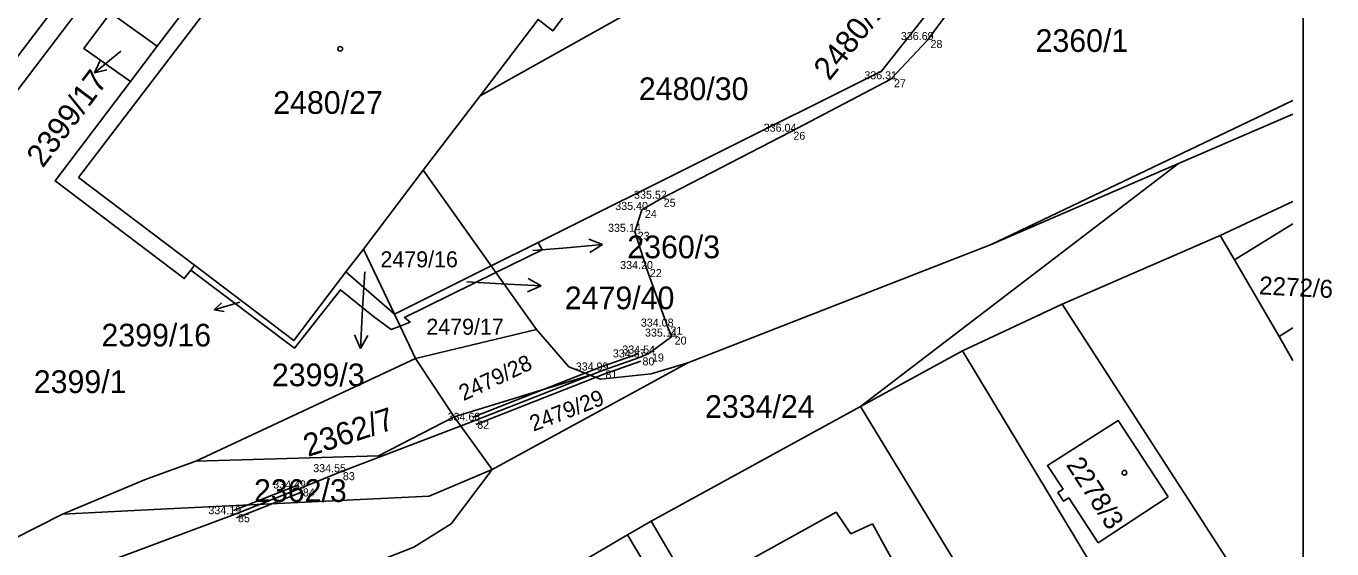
# Model space of a CAD drawing. Extents: x -606208 to -605570, y -1157873 to -1157573.
# Drawn here: x -605669 to -605571.1, y -1157686.5 to -1157647.4 of the extents above; entities that cross this region are included whole.
import ezdxf

# ---------------------------------------------------------------- set-up
doc = ezdxf.new("R2010")
doc.units = 0
for name, color, linetype in [('Vrstva 1', 7, 'Continuous'), ('Vrstva 30', 7, 'Continuous'), ('Vrstva 38', 7, 'Continuous'), ('Vrstva 58', 7, 'Continuous'), ('Vrstva 59', 7, 'Continuous'), ('Vrstva 60', 7, 'Continuous'), ('Vrstva 62', 7, 'Continuous')]:
    doc.layers.add(name, color=color, linetype=linetype)

msp = doc.modelspace()

# ---------------------------------------------------------------- linework, layer by layer
at = {"layer": 'Vrstva 1'}
msp.add_lwpolyline([(-606203.28, -1157873.46), (-605573.29, -1157873.46), (-605573.29, -1157576.47), (-606203.28, -1157576.47)], close=True, dxfattribs=at)
at = {"layer": 'Vrstva 30'}
msp.add_lwpolyline([(-605665.67, -1157688.53), (-605653.37, -1157683.93), (-605648.51, -1157682), (-605645.51, -1157680.78), (-605635.44, -1157676.93), (-605625.83, -1157673.16), (-605623.05, -1157672.18), (-605622.34, -1157671.89), (-605620.64, -1157670.62), (-605620.95, -1157669.87), (-605622.5, -1157665.56), (-605623.41, -1157662.77), (-605622.87, -1157661.13), (-605621.46, -1157660.29), (-605611.74, -1157655.27), (-605604.2, -1157651.34), (-605601.46, -1157648.4), (-605597.74, -1157643.37)], dxfattribs=at)
at = {"layer": 'Vrstva 38'}
for p, q in [((-605648.62, -1157681.72), (-605653.48, -1157683.65)), ((-605648.4, -1157682.28), (-605653.26, -1157684.21))]:
    msp.add_line(p, q, dxfattribs=at)
for points in [[(-605623.15, -1157671.9), (-605625.93, -1157672.88), (-605635.55, -1157676.65)], [(-605622.95, -1157672.46), (-605625.73, -1157673.44), (-605635.33, -1157677.21)]]:
    msp.add_lwpolyline(points, dxfattribs=at)
at = {"layer": 'Vrstva 60'}
for p, q in [((-605601.46, -1157648.4), (-605601.46, -1157648.4)), ((-605604.2, -1157651.34), (-605604.2, -1157651.34)), ((-605611.74, -1157655.27), (-605611.74, -1157655.27)), ((-605621.46, -1157660.29), (-605621.46, -1157660.29)), ((-605622.87, -1157661.13), (-605622.87, -1157661.13)), ((-605623.41, -1157662.77), (-605623.41, -1157662.77)), ((-605622.5, -1157665.56), (-605622.5, -1157665.56)), ((-605620.95, -1157669.87), (-605620.95, -1157669.87)), ((-605620.64, -1157670.62), (-605620.64, -1157670.62)), ((-605623.05, -1157672.18), (-605623.05, -1157672.18)), ((-605622.34, -1157671.89), (-605622.34, -1157671.89)), ((-605625.83, -1157673.16), (-605625.83, -1157673.16)), ((-605635.44, -1157676.93), (-605635.44, -1157676.93)), ((-605645.51, -1157680.78), (-605645.51, -1157680.78)), ((-605648.51, -1157682), (-605648.51, -1157682)), ((-605653.37, -1157683.93), (-605653.37, -1157683.93))]:
    msp.add_line(p, q, dxfattribs=at)
at = {"layer": 'Vrstva 62'}
for p, q in [((-605653.95, -1157631.43), (-605678, -1157663.1)), ((-605659.2, -1157648.85), (-605651.64, -1157638.87)), ((-605665.1, -1157658.71), (-605651.37, -1157640.68)), ((-605635, -1157652.57), (-605615.84, -1157641.85)), ((-605661.93, -1157649.24), (-605663.912, -1157650.845)), ((-605659.2, -1157648.85), (-605661.22, -1157651.51)), ((-605663.912, -1157650.845), (-605663.519, -1157649.979)), ((-605663.912, -1157650.845), (-605662.983, -1157650.64)), ((-605635, -1157652.57), (-605639.26, -1157658.16)), ((-605574.07, -1157652.93), (-605596.68, -1157663.73)), ((-605582.64, -1157657.66), (-605574.07, -1157653.96)), ((-605582.64, -1157657.66), (-605606.49, -1157675.87)), ((-605656.42, -1157665.28), (-605665.1, -1157658.71)), ((-605639.26, -1157658.16), (-605643.75, -1157664.06)), ((-605634.17, -1157665.31), (-605639.26, -1157658.16)), ((-605574.07, -1157660.5), (-605579.52, -1157663.05)), ((-605591.36, -1157668.19), (-605579.52, -1157663.05)), ((-605578.46, -1157664.86), (-605579.52, -1157663.05)), ((-605634.17, -1157665.31), (-605630.66, -1157663.56)), ((-605631.06, -1157664.17), (-605628.81, -1157663.99)), ((-605628.81, -1157663.99), (-605625.82, -1157663.728)), ((-605625.82, -1157663.728), (-605626.862, -1157663.317)), ((-605625.82, -1157663.728), (-605626.774, -1157664.315)), ((-605643.75, -1157664.06), (-605645.06, -1157665.78)), ((-605641.42, -1157668.93), (-605643.75, -1157664.06)), ((-605575.11, -1157670.61), (-605578.46, -1157664.86)), ((-605645.06, -1157665.78), (-605641.42, -1157668.93)), ((-605643.65, -1157665.76), (-605643.82, -1157668.52)), ((-605641.42, -1157668.93), (-605634.17, -1157665.31)), ((-605634.17, -1157665.31), (-605633.81, -1157665.82)), ((-605630.78, -1157670.08), (-605633.81, -1157665.82)), ((-605635.99, -1157666.52), (-605633.42, -1157666.66)), ((-605633.42, -1157666.66), (-605630.423, -1157666.817)), ((-605630.423, -1157666.817), (-605631.449, -1157667.265)), ((-605630.423, -1157666.817), (-605631.397, -1157666.265)), ((-605653, -1157668.05), (-605654.933, -1157668.604)), ((-605654.933, -1157668.604), (-605654.38, -1157668.097)), ((-605654.933, -1157668.604), (-605654.195, -1157668.742)), ((-605643.82, -1157668.52), (-605643.977, -1157671.517)), ((-605591.36, -1157668.19), (-605598.85, -1157671.69)), ((-605640.99, -1157669.83), (-605641.42, -1157668.93)), ((-605639.84, -1157672.25), (-605640.99, -1157669.83)), ((-605643.977, -1157671.517), (-605644.425, -1157670.491)), ((-605643.977, -1157671.517), (-605643.425, -1157670.543)), ((-605639.84, -1157672.25), (-605630.78, -1157670.08)), ((-605574.07, -1157672.4), (-605575.11, -1157670.61)), ((-605606.49, -1157675.87), (-605598.85, -1157671.69)), ((-605639.84, -1157672.25), (-605656.31, -1157679.96)), ((-605636.95, -1157676.63), (-605639.84, -1157672.25)), ((-605619.44, -1157672.59), (-605634.09, -1157680.59)), ((-605636.95, -1157676.63), (-605626.75, -1157673.51)), ((-605636.95, -1157676.63), (-605642.61, -1157679.56)), ((-605634.09, -1157680.59), (-605636.95, -1157676.63)), ((-605622.17, -1157684.45), (-605606.49, -1157675.87)), ((-605606.49, -1157675.87), (-605590.01, -1157702.84)), ((-605642.61, -1157679.56), (-605656.31, -1157679.96)), ((-605656.31, -1157679.96), (-605660.04, -1157681.31)), ((-605660.04, -1157681.31), (-605666.31, -1157683.93)), ((-605623.94, -1157685.48), (-605622.17, -1157684.45)), ((-605622.17, -1157684.45), (-605606.61, -1157711.04)), ((-605615.75, -1157687.9), (-605608.3, -1157683.78)), ((-605608.3, -1157683.78), (-605607.2, -1157685.39)), ((-605636.65, -1157692.89), (-605623.94, -1157685.48)), ((-605623.94, -1157685.48), (-605615.89, -1157699.06)), ((-605607.2, -1157685.39), (-605605.59, -1157684.64)), ((-605605.59, -1157684.64), (-605601.39, -1157692.27))]:
    msp.add_line(p, q, dxfattribs=at)
for points in [[(-605714.75, -1157700.25), (-605710.96, -1157695.68), (-605710.18, -1157694.65), (-605706.94, -1157690.4), (-605702.43, -1157684.48), (-605699.9, -1157681.15), (-605696.13, -1157676.2), (-605691.65, -1157670.31), (-605690.12, -1157670.1), (-605687.04, -1157672.45), (-605682.78, -1157666.84), (-605681.4, -1157665.03), (-605679.37, -1157662.36), (-605660.55, -1157637.61), (-605653.28, -1157627.99)], [(-605621.69, -1157637.35), (-605629.56, -1157647.72), (-605630.66, -1157646.86), (-605635, -1157652.57)], [(-605599.92, -1157644.4), (-605604.92, -1157650.72), (-605630.66, -1157663.56)], [(-605661.22, -1157651.51), (-605664.71, -1157649.03), (-605662.71, -1157646.36), (-605659.2, -1157648.85)], [(-605656.69, -1157665.64), (-605657.18, -1157666.27), (-605666.86, -1157658.96), (-605661.22, -1157651.51)], [(-605619.44, -1157672.59), (-605596.68, -1157663.73), (-605582.64, -1157657.66)], [(-605578.46, -1157664.86), (-605574.07, -1157662.17)], [(-605630.66, -1157663.56), (-605630.36, -1157664.12), (-605633.81, -1157665.82)], [(-605656.69, -1157665.64), (-605656.42, -1157665.28), (-605648.97, -1157670.92), (-605645.06, -1157665.78)], [(-605640.99, -1157669.83), (-605641.66, -1157670.1), (-605642.98, -1157669.11), (-605645.47, -1157667.11), (-605648.92, -1157671.49), (-605656.69, -1157665.64)], [(-605633.81, -1157665.82), (-605640.68, -1157669.2), (-605640.25, -1157669.53), (-605640.99, -1157669.83)], [(-605591.36, -1157668.19), (-605574.07, -1157694.95)], [(-605626.75, -1157673.51), (-605628.34, -1157672.88), (-605630.78, -1157670.08)], [(-605574.07, -1157669.97), (-605575.11, -1157670.61)], [(-605574.07, -1157711.46), (-605582.64, -1157698.54), (-605598.85, -1157671.69)], [(-605619.44, -1157672.59), (-605622.17, -1157673.4), (-605625.98, -1157673.81), (-605626.75, -1157673.51)], [(-605583.41, -1157682.62), (-605588.67, -1157686.07), (-605590.88, -1157682.71), (-605591.26, -1157682.96), (-605591.69, -1157682.31), (-605591.3, -1157682.05), (-605592.47, -1157680.28), (-605587.17, -1157676.9), (-605583.41, -1157682.62)], [(-605634.09, -1157680.59), (-605637.18, -1157684.66), (-605639.98, -1157686.4), (-605673.75, -1157699.63)], [(-605634.09, -1157680.59), (-605638.82, -1157682.58), (-605658.45, -1157683.53), (-605666.31, -1157683.93)], [(-605666.31, -1157683.93), (-605670.06, -1157685.83), (-605679.01, -1157689.56)]]:
    msp.add_lwpolyline(points, dxfattribs=at)
for centre in [(-605645.487, -1157649.059), (-605586.697, -1157680.819)]:
    msp.add_circle(centre, 0.175, dxfattribs=at)

# ---------------------------------------------------------------- texts
at = {"layer": 'Vrstva 58'}
for s, p in [('336.69 ', (-605603.46, -1157648.4)), ('336.31 ', (-605606.2, -1157651.34)), ('336.04 ', (-605613.74, -1157655.27)), ('335.52 ', (-605623.46, -1157660.29)), ('335.40 ', (-605624.87, -1157661.13)), ('335.14 ', (-605625.41, -1157662.77)), ('334.20 ', (-605624.5, -1157665.56)), ('334.08 ', (-605622.95, -1157669.87)), ('335.11 ', (-605622.64, -1157670.62)), ('334.87 ', (-605625.05, -1157672.18)), ('334.54 ', (-605624.34, -1157671.89)), ('334.99 ', (-605627.83, -1157673.16)), ('334.68 ', (-605637.44, -1157676.93)), ('334.55 ', (-605647.51, -1157680.78)), ('334.49 ', (-605650.51, -1157682)), ('334.19 ', (-605655.37, -1157683.93))]:
    msp.add_text(s, height=0.6, dxfattribs=at).set_placement(p)
at = {"layer": 'Vrstva 59'}
for s, p in [(' 28', (-605601.46, -1157649)), (' 27', (-605604.2, -1157651.94)), (' 26', (-605611.74, -1157655.87)), (' 25', (-605621.46, -1157660.89)), (' 24', (-605622.87, -1157661.73)), (' 23', (-605623.41, -1157663.37)), (' 22', (-605622.5, -1157666.16)), (' 21', (-605620.95, -1157670.47)), (' 20', (-605620.64, -1157671.22)), (' 80', (-605623.05, -1157672.78)), (' 19', (-605622.34, -1157672.49)), (' 81', (-605625.83, -1157673.76)), (' 82', (-605635.44, -1157677.53)), (' 83', (-605645.51, -1157681.38)), (' 84', (-605648.51, -1157682.6)), (' 85', (-605653.37, -1157684.53))]:
    msp.add_text(s, height=0.6, dxfattribs=at).set_placement(p)
at = {"layer": 'Vrstva 62'}
for s, height, rotation, p in [('2480/121', 1.7, 51, (-605608.82, -1157651.515)), ('2399/17', 1.7, 53, (-605667.78, -1157658.043)), ('2272/6', 1.354, 357, (-605576.633, -1157667.451)), ('2479/28', 1.2, 25, (-605636.24, -1157675.46)), ('2479/29', 1.2, 21, (-605631.01, -1157677.75)), ('2362/7', 1.7, 18, (-605647.91, -1157679.65)), ('2278/3', 1.452, 303, (-605591.11, -1157680.229))]:
    msp.add_text(s, height=height, rotation=rotation, dxfattribs=at).set_placement(p)
for s, height, p in [('2360/1', 1.7, (-605593.362, -1157649.29)), ('2480/30', 1.7, (-605623.1, -1157652.9)), ('2480/27', 1.7, (-605650.51, -1157653.93)), ('2360/3', 1.7, (-605623.967, -1157664.75)), ('2479/16', 1.2, (-605642.47, -1157665.43)), ('2479/40', 1.7, (-605628.652, -1157668.57)), ('2399/16', 1.7, (-605663.384, -1157671.36)), ('2479/17', 1.2, (-605639.03, -1157670.48)), ('2399/3', 1.7, (-605650.61, -1157674.34)), ('2399/1', 1.7, (-605668.46, -1157674.85)), ('2334/24', 1.7, (-605618.14, -1157676.71)), ('2362/3', 1.7, (-605651.95, -1157683.01))]:
    msp.add_text(s, height=height, dxfattribs=at).set_placement(p)

doc.saveas('drawing.dxf')
